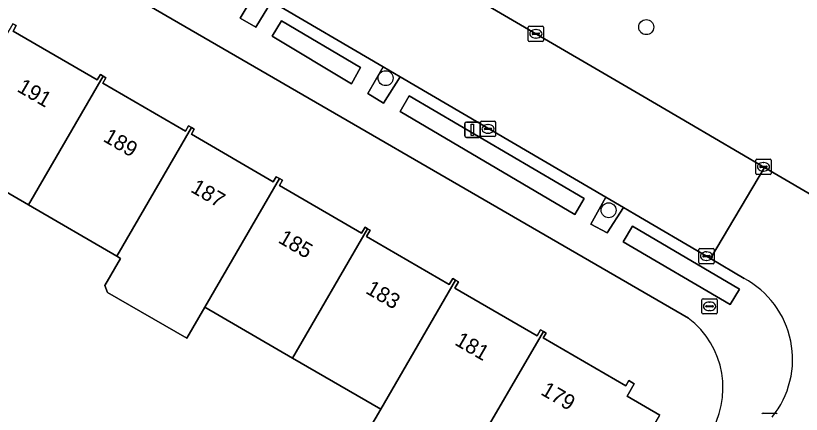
# Model space of a CAD drawing. Extents: x 160157 to 160921, y 381516 to 382045.
# Drawn here: x 160661.8 to 160713.1, y 381836.5 to 381862.5 of the extents above; entities that cross this region are included whole.
import ezdxf

# ---------------------------------------------------------------- set-up
doc = ezdxf.new("R2010")
doc.units = 0
for name, color, linetype in [('IMGEO_Berm_groen', 7, 'Continuous'), ('IMGEO_Boom', 7, 'Continuous'), ('IMGEO_Brandkraan', 7, 'Continuous'), ('IMGEO_Erf', 7, 'Continuous'), ('IMGEO_Groenvoorziening', 7, 'Continuous'), ('IMGEO_Kolk', 7, 'Continuous'), ('IMGEO_Lichtmast', 7, 'Continuous'), ('IMGEO_Pand', 7, 'Continuous'), ('IMGEO_Pand_nummerreeks', 7, 'Continuous'), ('IMGEO_Rijbaan_lokaal_open', 7, 'Continuous'), ('IMGEO_Voetpad_open', 7, 'Continuous')]:
    doc.layers.add(name, color=color, linetype=linetype)

msp = doc.modelspace()

# ---------------------------------------------------------------- linework, layer by layer
at = {"layer": 'IMGEO_Berm_groen'}
msp.add_lwpolyline([(160668.049, 381877.62), (160668.247, 381877.503), (160668.279, 381877.484), (160673.61, 381874.339), (160685.249, 381867.536), (160702.79, 381857.283), (160705.838, 381855.502), (160710.739, 381852.616), (160729.517, 381841.642), (160729.683, 381841.537), (160737.491, 381836.968), (160750, 381829.655), (160770.407, 381817.758), (160781.21, 381811.887)], dxfattribs=at)
at = {"layer": 'IMGEO_Boom'}
for centre in [(160703.019, 381861.791), (160685.997, 381858.458), (160700.565, 381849.831)]:
    msp.add_circle(centre, 0.489, dxfattribs=at)
at = {"layer": 'IMGEO_Brandkraan'}
for p, q in [((160706.731, 381844.054), (160707.583, 381844.054)), ((160706.656, 381843.128), (160706.656, 381843.98)), ((160706.915, 381843.548), (160706.915, 381843.56)), ((160707.353, 381843.511), (160706.955, 381843.511)), ((160706.958, 381843.597), (160707.356, 381843.597)), ((160707.144, 381843.834), (160707.169, 381843.834)), ((160707.399, 381843.56), (160707.399, 381843.548)), ((160707.657, 381843.98), (160707.657, 381843.128)), ((160707.583, 381843.054), (160706.731, 381843.054)), ((160707.167, 381843.274), (160707.142, 381843.274))]:
    msp.add_line(p, q, dxfattribs=at)
for points in [[(160706.731, 381844.054), (160707.583, 381844.054)], [(160706.656, 381843.128), (160706.656, 381843.98)], [(160707.657, 381843.98), (160707.657, 381843.128)], [(160707.583, 381843.054), (160706.731, 381843.054)]]:
    msp.add_lwpolyline(points, dxfattribs=at)
for centre, radius, start, end in [((160706.733, 381843.978), 0.0765, 91.552, 178.448), ((160706.733, 381843.978), 0.0765, 91.552, 178.448), ((160707.581, 381843.978), 0.0765, 1.552, 88.448), ((160707.581, 381843.978), 0.0765, 1.552, 88.448), ((160706.955, 381843.557), 0.0403, 85.8775, 175.7526), ((160706.952, 381843.547), 0.0366, 178.938, 274.7102), ((160707.356, 381843.554), 0.043, 264.8664, 352.4533), ((160707.36, 381843.559), 0.0386, 1.7309, 96.639), ((160706.733, 381843.13), 0.0765, 181.552, 268.448), ((160706.733, 381843.13), 0.0765, 181.552, 268.448), ((160707.581, 381843.13), 0.0765, 271.552, 358.448), ((160707.581, 381843.13), 0.0765, 271.552, 358.448)]:
    msp.add_arc(centre, radius, start, end, dxfattribs=at)
for centre, major_axis, ratio, start_param, end_param in [((160707.143, 381843.554), (-0.387, 0.002), 0.722429, 4.712389, 7.853982), ((160707.168, 381843.554), (-0.39, 0.002), 0.717154, 1.570796, 4.712389)]:
    msp.add_ellipse(centre, major_axis=major_axis, ratio=ratio, start_param=start_param, end_param=end_param, dxfattribs=at)
at = {"layer": 'IMGEO_Erf'}
for points in [[(160705.77, 381842.782), (160667.654, 381864.886), (160664.857, 381866.115), (160662.715, 381866.57), (160660.296, 381866.624)], [(160661.65, 381862.014), (160661.869, 381861.887), (160661.664, 381861.534), (160667.164, 381858.345), (160667.363, 381858.688), (160667.544, 381858.583), (160667.725, 381858.478), (160667.518, 381858.121), (160672.924, 381854.985), (160673.126, 381855.334), (160673.31, 381855.228), (160673.497, 381855.119), (160673.308, 381854.793), (160678.661, 381851.689), (160678.854, 381852.023), (160679.059, 381851.904), (160679.264, 381851.785), (160679.068, 381851.447), (160684.431, 381848.337), (160684.654, 381848.722), (160684.823, 381848.624), (160684.991, 381848.527), (160684.753, 381848.115), (160690.156, 381844.982), (160690.384, 381845.375), (160690.571, 381845.267), (160690.758, 381845.159), (160690.52, 381844.749), (160695.896, 381841.632), (160696.119, 381842.016), (160696.301, 381841.911), (160696.48, 381841.807), (160696.295, 381841.489), (160701.682, 381838.365), (160701.879, 381838.705), (160702.24, 381838.495), (160701.768, 381837.681), (160703.91, 381836.439)], [(160684.21, 381834.303), (160685.678, 381836.834), (160679.919, 381840.173), (160674.182, 381843.499), (160673.004, 381841.469), (160667.839, 381844.466), (160667.655, 381844.919), (160668.683, 381846.689), (160668.437, 381846.831), (160662.665, 381850.178), (160656.769, 381853.597)]]:
    msp.add_lwpolyline(points, dxfattribs=at)
msp.add_arc((160702.334, 381838.235), 5.699, 326.3418, 52.9251, dxfattribs=at)
at = {"layer": 'IMGEO_Groenvoorziening'}
for points in [[(160678.543, 381863.458), (160677.504, 381864.065), (160676.497, 381862.385), (160677.53, 381861.789)], [(160684.366, 381859.148), (160679.193, 381862.211), (160678.596, 381861.211), (160683.778, 381858.097)], [(160686.956, 381858.54), (160685.845, 381859.19), (160684.83, 381857.452), (160685.866, 381856.834)], [(160698.96, 381850.597), (160687.525, 381857.312), (160686.939, 381856.273), (160698.359, 381849.562)], [(160701.54, 381850.015), (160700.385, 381850.69), (160699.408, 381848.914), (160700.467, 381848.352)], [(160709.104, 381844.679), (160702.115, 381848.787), (160701.521, 381847.774), (160708.504, 381843.678)]]:
    msp.add_lwpolyline(points, close=True, dxfattribs=at)
at = {"layer": 'IMGEO_Kolk'}
for p, q in [((160695.31, 381860.928), (160695.31, 381861.78)), ((160695.385, 381861.854), (160696.237, 381861.854)), ((160695.798, 381861.634), (160695.823, 381861.634)), ((160696.311, 381861.78), (160696.311, 381860.928)), ((160695.569, 381861.348), (160695.569, 381861.36)), ((160696.007, 381861.311), (160695.609, 381861.311)), ((160695.612, 381861.397), (160696.01, 381861.397)), ((160695.821, 381861.074), (160695.796, 381861.074)), ((160696.053, 381861.36), (160696.053, 381861.348)), ((160696.237, 381860.854), (160695.385, 381860.854)), ((160692.184, 381854.718), (160692.184, 381855.57)), ((160692.259, 381855.644), (160693.111, 381855.644)), ((160692.672, 381855.424), (160692.697, 381855.424)), ((160693.185, 381855.57), (160693.185, 381854.718)), ((160692.443, 381855.138), (160692.443, 381855.15)), ((160692.881, 381855.101), (160692.483, 381855.101)), ((160692.486, 381855.187), (160692.884, 381855.187)), ((160692.695, 381854.864), (160692.67, 381854.864)), ((160692.927, 381855.15), (160692.927, 381855.138)), ((160693.111, 381854.644), (160692.259, 381854.644)), ((160710.178, 381852.241), (160710.178, 381853.093)), ((160710.253, 381853.167), (160711.105, 381853.167)), ((160710.666, 381852.947), (160710.691, 381852.947)), ((160711.179, 381853.093), (160711.179, 381852.241)), ((160710.437, 381852.661), (160710.437, 381852.673)), ((160710.875, 381852.624), (160710.477, 381852.624)), ((160710.48, 381852.71), (160710.878, 381852.71)), ((160710.689, 381852.387), (160710.664, 381852.387)), ((160710.921, 381852.673), (160710.921, 381852.661)), ((160711.105, 381852.167), (160710.253, 381852.167)), ((160706.456, 381846.407), (160706.456, 381847.259)), ((160706.531, 381847.333), (160707.383, 381847.333)), ((160706.944, 381847.113), (160706.969, 381847.113)), ((160707.457, 381847.259), (160707.457, 381846.407)), ((160706.715, 381846.827), (160706.715, 381846.839)), ((160707.153, 381846.79), (160706.755, 381846.79)), ((160706.758, 381846.876), (160707.156, 381846.876)), ((160707.199, 381846.839), (160707.199, 381846.827)), ((160707.383, 381846.333), (160706.531, 381846.333)), ((160706.967, 381846.553), (160706.942, 381846.553)), ((160710.653, 381836.577), (160711.505, 381836.577))]:
    msp.add_line(p, q, dxfattribs=at)
for points in [[(160695.31, 381860.928), (160695.31, 381861.78)], [(160695.385, 381861.854), (160696.237, 381861.854)], [(160696.311, 381861.78), (160696.311, 381860.928)], [(160696.237, 381860.854), (160695.385, 381860.854)], [(160692.184, 381854.718), (160692.184, 381855.57)], [(160692.259, 381855.644), (160693.111, 381855.644)], [(160693.185, 381855.57), (160693.185, 381854.718)], [(160693.111, 381854.644), (160692.259, 381854.644)], [(160710.178, 381852.241), (160710.178, 381853.093)], [(160710.253, 381853.167), (160711.105, 381853.167)], [(160711.179, 381853.093), (160711.179, 381852.241)], [(160711.105, 381852.167), (160710.253, 381852.167)], [(160706.456, 381846.407), (160706.456, 381847.259)], [(160706.531, 381847.333), (160707.383, 381847.333)], [(160707.457, 381847.259), (160707.457, 381846.407)], [(160707.383, 381846.333), (160706.531, 381846.333)], [(160710.653, 381836.577), (160711.505, 381836.577)]]:
    msp.add_lwpolyline(points, dxfattribs=at)
for centre, radius, start, end in [((160695.387, 381861.778), 0.0765, 91.552, 178.448), ((160695.387, 381861.778), 0.0765, 91.552, 178.448), ((160696.235, 381861.778), 0.0765, 1.552, 88.448), ((160696.235, 381861.778), 0.0765, 1.552, 88.448), ((160695.609, 381861.357), 0.0403, 85.8775, 175.7526), ((160695.606, 381861.347), 0.0366, 178.938, 274.7102), ((160696.01, 381861.354), 0.043, 264.8664, 352.4533), ((160696.014, 381861.359), 0.0386, 1.7309, 96.639), ((160695.387, 381860.93), 0.0765, 181.552, 268.448), ((160695.387, 381860.93), 0.0765, 181.552, 268.448), ((160696.235, 381860.93), 0.0765, 271.552, 358.448), ((160696.235, 381860.93), 0.0765, 271.552, 358.448), ((160692.261, 381855.568), 0.0765, 91.552, 178.448), ((160692.261, 381855.568), 0.0765, 91.552, 178.448), ((160693.109, 381855.568), 0.0765, 1.552, 88.448), ((160693.109, 381855.568), 0.0765, 1.552, 88.448), ((160692.483, 381855.147), 0.0403, 85.8775, 175.7526), ((160692.48, 381855.137), 0.0366, 178.938, 274.7102), ((160692.884, 381855.144), 0.043, 264.8664, 352.4533), ((160692.888, 381855.149), 0.0386, 1.7309, 96.639), ((160692.261, 381854.72), 0.0765, 181.552, 268.448), ((160692.261, 381854.72), 0.0765, 181.552, 268.448), ((160693.109, 381854.72), 0.0765, 271.552, 358.448), ((160693.109, 381854.72), 0.0765, 271.552, 358.448), ((160710.255, 381853.091), 0.0765, 91.552, 178.448), ((160710.255, 381853.091), 0.0765, 91.552, 178.448), ((160711.103, 381853.091), 0.0765, 1.552, 88.448), ((160711.103, 381853.091), 0.0765, 1.552, 88.448), ((160710.255, 381852.243), 0.0765, 181.552, 268.448), ((160710.255, 381852.243), 0.0765, 181.552, 268.448), ((160710.477, 381852.67), 0.0403, 85.8775, 175.7526), ((160710.474, 381852.66), 0.0366, 178.938, 274.7102), ((160710.878, 381852.667), 0.043, 264.8664, 352.4533), ((160710.882, 381852.672), 0.0386, 1.7309, 96.639), ((160711.103, 381852.243), 0.0765, 271.552, 358.448), ((160711.103, 381852.243), 0.0765, 271.552, 358.448), ((160706.533, 381847.257), 0.0765, 91.552, 178.448), ((160706.533, 381847.257), 0.0765, 91.552, 178.448), ((160707.381, 381847.257), 0.0765, 1.552, 88.448), ((160707.381, 381847.257), 0.0765, 1.552, 88.448), ((160706.755, 381846.836), 0.0403, 85.8775, 175.7526), ((160706.752, 381846.826), 0.0366, 178.938, 274.7102), ((160707.156, 381846.833), 0.043, 264.8664, 352.4533), ((160707.16, 381846.838), 0.0386, 1.7309, 96.639), ((160706.533, 381846.409), 0.0765, 181.552, 268.448), ((160706.533, 381846.409), 0.0765, 181.552, 268.448), ((160707.381, 381846.409), 0.0765, 271.552, 358.448), ((160707.381, 381846.409), 0.0765, 271.552, 358.448), ((160710.655, 381836.501), 0.0765, 91.552, 178.448), ((160710.655, 381836.501), 0.0765, 91.552, 178.448), ((160711.503, 381836.501), 0.0765, 1.552, 88.448), ((160711.503, 381836.501), 0.0765, 1.552, 88.448)]:
    msp.add_arc(centre, radius, start, end, dxfattribs=at)
for centre, major_axis, ratio, start_param, end_param in [((160695.797, 381861.354), (-0.387, 0.002), 0.722429, 4.712389, 7.853982), ((160695.822, 381861.354), (-0.39, 0.002), 0.717154, 1.570796, 4.712389), ((160692.671, 381855.144), (-0.387, 0.002), 0.722429, 4.712389, 7.853982), ((160692.696, 381855.144), (-0.39, 0.002), 0.717154, 1.570796, 4.712389), ((160710.665, 381852.667), (-0.387, 0.002), 0.722429, 4.712389, 7.853982), ((160710.69, 381852.667), (-0.39, 0.002), 0.717154, 1.570796, 4.712389), ((160706.943, 381846.833), (-0.387, 0.002), 0.722429, 4.712389, 7.853982), ((160706.968, 381846.833), (-0.39, 0.002), 0.717154, 1.570796, 4.712389)]:
    msp.add_ellipse(centre, major_axis=major_axis, ratio=ratio, start_param=start_param, end_param=end_param, dxfattribs=at)
at = {"layer": 'IMGEO_Lichtmast'}
for p, q in [((160691.172, 381854.688), (160691.172, 381855.488)), ((160691.172, 381855.488), (160691.172, 381854.688)), ((160691.272, 381855.588), (160692.062, 381855.588)), ((160692.062, 381855.588), (160691.272, 381855.588)), ((160692.162, 381855.488), (160692.162, 381854.688)), ((160692.162, 381854.688), (160692.162, 381855.488)), ((160692.062, 381854.588), (160691.272, 381854.588)), ((160691.272, 381854.588), (160692.062, 381854.588))]:
    msp.add_line(p, q, dxfattribs=at)
msp.add_lwpolyline([(160691.592, 381855.463), (160691.742, 381855.463), (160691.742, 381854.713), (160691.592, 381854.713), (160691.592, 381855.463)], dxfattribs=at)
for centre, start, end in [((160691.272, 381855.488), 90, 180), ((160691.272, 381855.488), 90, 180), ((160692.062, 381855.488), 0, 90), ((160692.062, 381855.488), 360, 90), ((160691.272, 381854.688), 180, 270), ((160691.272, 381854.688), 180, 270), ((160692.062, 381854.688), 270, 0), ((160692.062, 381854.688), 270, 0)]:
    msp.add_arc(centre, 0.1, start, end, dxfattribs=at)
at = {"layer": 'IMGEO_Pand'}
for points in [[(160662.665, 381850.178), (160667.544, 381858.583), (160667.363, 381858.688), (160667.164, 381858.345), (160661.664, 381861.534), (160661.869, 381861.887), (160661.65, 381862.014), (160660.898, 381860.716), (160656.769, 381853.597)], [(160673.31, 381855.228), (160673.126, 381855.334), (160672.924, 381854.985), (160667.518, 381858.121), (160667.725, 381858.478), (160667.544, 381858.583), (160662.665, 381850.178), (160668.437, 381846.831)], [(160679.059, 381851.904), (160678.854, 381852.023), (160678.661, 381851.689), (160673.308, 381854.793), (160673.497, 381855.119), (160673.31, 381855.228), (160668.437, 381846.831), (160668.683, 381846.689), (160667.655, 381844.919), (160667.839, 381844.466), (160673.004, 381841.469), (160674.182, 381843.499)], [(160679.059, 381851.904), (160674.182, 381843.499), (160679.919, 381840.173), (160684.823, 381848.624), (160684.654, 381848.722), (160684.431, 381848.337), (160679.068, 381851.447), (160679.264, 381851.785)], [(160690.571, 381845.267), (160690.384, 381845.375), (160690.156, 381844.982), (160684.753, 381848.115), (160684.991, 381848.527), (160684.823, 381848.624), (160679.919, 381840.173), (160685.678, 381836.834)], [(160696.301, 381841.911), (160696.119, 381842.016), (160695.896, 381841.632), (160690.52, 381844.749), (160690.758, 381845.159), (160690.571, 381845.267), (160685.678, 381836.834), (160684.21, 381834.303), (160689.953, 381830.972), (160690.32, 381831.604), (160691.421, 381833.503)], [(160691.421, 381833.503), (160697.333, 381830.075), (160699.968, 381834.618), (160702.128, 381833.366), (160703.91, 381836.439), (160701.768, 381837.681), (160702.24, 381838.495), (160701.879, 381838.705), (160701.682, 381838.365), (160696.295, 381841.489), (160696.48, 381841.807), (160696.301, 381841.911)]]:
    msp.add_lwpolyline(points, close=True, dxfattribs=at)
at = {"layer": 'IMGEO_Rijbaan_lokaal_open'}
for points in [[(160661.295, 381873.542), (160664.089, 381871.908), (160667.275, 381870.045), (160672.126, 381867.209), (160677.504, 381864.065), (160678.543, 381863.458), (160685.845, 381859.19), (160686.956, 381858.54), (160700.385, 381850.69), (160701.54, 381850.015), (160702.286, 381849.579), (160706.957, 381846.834), (160707.215, 381846.678), (160710.739, 381852.616), (160705.838, 381855.502), (160702.79, 381857.283), (160685.249, 381867.536), (160673.61, 381874.339), (160668.279, 381877.484), (160668.247, 381877.503), (160668.049, 381877.62)], [(160729.517, 381841.642), (160710.739, 381852.616), (160707.215, 381846.678), (160709.408, 381845.374)]]:
    msp.add_lwpolyline(points, dxfattribs=at)
msp.add_arc((160706.596, 381840.091), 5.985, 321.0131, 61.9743, dxfattribs=at)
at = {"layer": 'IMGEO_Voetpad_open'}
for points in [[(160653.838, 381873.223), (160653.156, 381872.105), (160664.857, 381866.115), (160667.654, 381864.886), (160705.77, 381842.782)], [(160709.408, 381845.374), (160707.215, 381846.678), (160706.957, 381846.834), (160702.286, 381849.579), (160701.54, 381850.015), (160700.467, 381848.352), (160699.408, 381848.914), (160700.385, 381850.69), (160686.956, 381858.54), (160685.866, 381856.834), (160684.83, 381857.452), (160685.845, 381859.19), (160678.543, 381863.458), (160677.53, 381861.789), (160676.497, 381862.385), (160677.504, 381864.065), (160672.126, 381867.209), (160667.275, 381870.045), (160664.089, 381871.908)]]:
    msp.add_lwpolyline(points, dxfattribs=at)
for points in [[(160678.596, 381861.211), (160679.193, 381862.211), (160684.366, 381859.148), (160683.778, 381858.097)], [(160686.939, 381856.273), (160687.525, 381857.312), (160698.96, 381850.597), (160698.359, 381849.562)], [(160702.115, 381848.787), (160709.104, 381844.679), (160708.504, 381843.678), (160701.521, 381847.774)]]:
    msp.add_lwpolyline(points, close=True, dxfattribs=at)
for centre, radius, start, end in [((160706.596, 381840.091), 5.985, 321.0131, 61.9743), ((160702.334, 381838.235), 5.699, 326.3418, 52.9251)]:
    msp.add_arc(centre, radius, start, end, dxfattribs=at)

# ---------------------------------------------------------------- texts
at = {"layer": 'IMGEO_Pand_nummerreeks'}
for s, rotation, p in [('191', 329.9307, (160661.863, 381857.628)), ('189', 329.9307, (160667.481, 381854.376)), ('187', 329.9312, (160673.199, 381851.066)), ('185', 329.9307, (160678.915, 381847.757)), ('183', 329.9307, (160684.632, 381844.447)), ('181', 329.9312, (160690.449, 381841.078)), ('179', 329.9307, (160696.066, 381837.827))]:
    msp.add_text(s, height=1, rotation=rotation, dxfattribs=at).set_placement(p)

doc.saveas('drawing.dxf')
